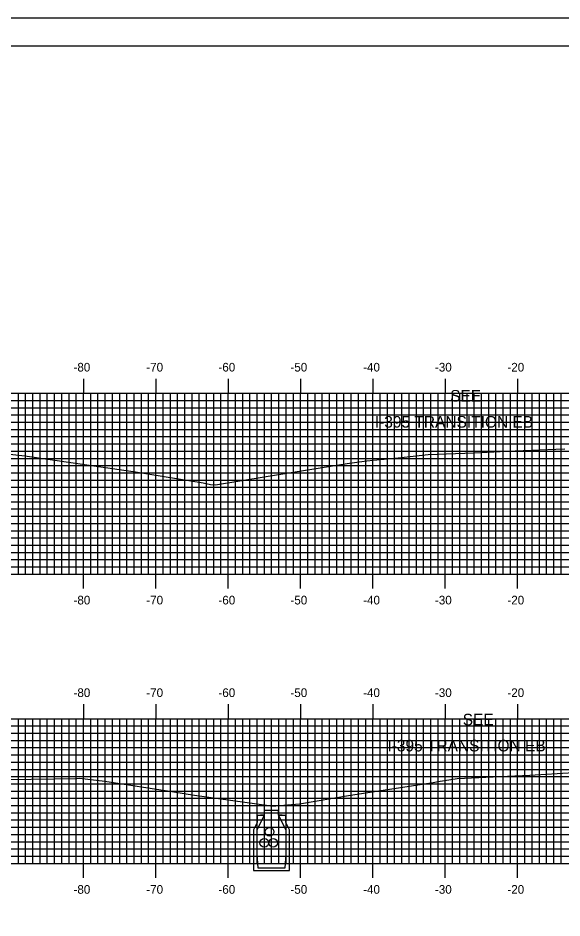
# Model space of a CAD drawing. Extents: x 842175 to 842518, y 363538 to 363758.
# Drawn here: x 842251.8 to 842327, y 363633.2 to 363757.6 of the extents above; entities that cross this region are included whole.
import ezdxf

# ---------------------------------------------------------------- set-up
doc = ezdxf.new("R2010")
doc.units = 0
for name, color, linetype in [('ANNOTATION', 7, 'Continuous'), ('BORDER', 7, 'Continuous'), ('H_V ANNOTATION', 7, 'Continuous'), ('MAJOR', 7, 'Continuous'), ('MINOR', 7, 'Continuous'), ('PLOT BOUNDARY', 7, 'Continuous'), ('S_Drainage_CB', 7, 'Continuous'), ('S_Drainage_Invert', 7, 'Continuous'), ('S_Roadway_Centerline', 7, 'Continuous')]:
    doc.layers.add(name, color=color, linetype=linetype)

msp = doc.modelspace()

# ---------------------------------------------------------------- linework, layer by layer
at = {"layer": 'BORDER'}
msp.add_lwpolyline([(842191.29, 363543.72), (842511.29, 363543.72), (842511.29, 363753.72), (842191.29, 363753.72)], close=True, dxfattribs=at)
at = {"layer": 'MAJOR'}
for p, q in [((842260.89, 363707.73), (842260.89, 363705.72)), ((842270.89, 363707.73), (842270.89, 363705.72)), ((842280.89, 363707.73), (842280.89, 363705.72)), ((842290.89, 363707.73), (842290.89, 363705.72)), ((842300.89, 363707.73), (842300.89, 363705.72)), ((842310.89, 363707.73), (842310.89, 363705.72)), ((842320.89, 363707.73), (842320.89, 363705.72)), ((842200.89, 363705.72), (842480.89, 363705.72)), ((842200.89, 363705.72), (842480.89, 363705.72)), ((842260.89, 363680.72), (842260.89, 363705.72)), ((842270.89, 363680.72), (842270.89, 363705.72)), ((842280.89, 363680.72), (842280.89, 363705.72)), ((842290.89, 363680.72), (842290.89, 363705.72)), ((842300.89, 363680.72), (842300.89, 363705.72)), ((842310.89, 363680.72), (842310.89, 363705.72)), ((842320.89, 363680.72), (842320.89, 363705.72)), ((842200.89, 363700.72), (842480.89, 363700.72)), ((842200.89, 363695.72), (842480.89, 363695.72)), ((842200.89, 363690.72), (842480.89, 363690.72)), ((842200.89, 363685.72), (842480.89, 363685.72)), ((842200.89, 363680.72), (842480.89, 363680.72)), ((842200.89, 363680.72), (842480.89, 363680.72)), ((842260.89, 363678.72), (842260.89, 363680.72)), ((842270.89, 363678.72), (842270.89, 363680.72)), ((842280.89, 363678.72), (842280.89, 363680.72)), ((842290.89, 363678.72), (842290.89, 363680.72)), ((842300.89, 363678.72), (842300.89, 363680.72)), ((842310.89, 363678.72), (842310.89, 363680.72)), ((842320.89, 363678.72), (842320.89, 363680.72)), ((842260.89, 363662.73), (842260.89, 363660.72)), ((842270.89, 363662.73), (842270.89, 363660.72)), ((842280.89, 363662.73), (842280.89, 363660.72)), ((842290.89, 363662.73), (842290.89, 363660.72)), ((842300.89, 363662.73), (842300.89, 363660.72)), ((842310.89, 363662.73), (842310.89, 363660.72)), ((842320.89, 363662.73), (842320.89, 363660.72)), ((842200.89, 363660.72), (842480.89, 363660.72)), ((842200.89, 363660.72), (842480.89, 363660.72)), ((842260.89, 363640.72), (842260.89, 363660.72)), ((842270.89, 363640.72), (842270.89, 363660.72)), ((842280.89, 363640.72), (842280.89, 363660.72)), ((842290.89, 363640.72), (842290.89, 363660.72)), ((842300.89, 363640.72), (842300.89, 363660.72)), ((842310.89, 363640.72), (842310.89, 363660.72)), ((842320.89, 363640.72), (842320.89, 363660.72)), ((842200.89, 363655.72), (842480.89, 363655.72)), ((842200.89, 363650.72), (842480.89, 363650.72)), ((842200.89, 363645.72), (842480.89, 363645.72)), ((842200.89, 363640.72), (842480.89, 363640.72)), ((842200.89, 363640.72), (842480.89, 363640.72)), ((842260.89, 363638.72), (842260.89, 363640.72)), ((842270.89, 363638.72), (842270.89, 363640.72)), ((842280.89, 363638.72), (842280.89, 363640.72)), ((842290.89, 363638.72), (842290.89, 363640.72)), ((842300.89, 363638.72), (842300.89, 363640.72)), ((842310.89, 363638.72), (842310.89, 363640.72)), ((842320.89, 363638.72), (842320.89, 363640.72))]:
    msp.add_line(p, q, dxfattribs=at)
at = {"layer": 'MINOR'}
for p, q in [((842251.89, 363680.72), (842251.89, 363705.72)), ((842252.89, 363680.72), (842252.89, 363705.72)), ((842253.89, 363680.72), (842253.89, 363705.72)), ((842254.89, 363680.72), (842254.89, 363705.72)), ((842255.89, 363680.72), (842255.89, 363705.72)), ((842256.89, 363680.72), (842256.89, 363705.72)), ((842257.89, 363680.72), (842257.89, 363705.72)), ((842258.89, 363680.72), (842258.89, 363705.72)), ((842259.89, 363680.72), (842259.89, 363705.72)), ((842261.89, 363680.72), (842261.89, 363705.72)), ((842262.89, 363680.72), (842262.89, 363705.72)), ((842263.89, 363680.72), (842263.89, 363705.72)), ((842264.89, 363680.72), (842264.89, 363705.72)), ((842265.89, 363680.72), (842265.89, 363705.72)), ((842266.89, 363680.72), (842266.89, 363705.72)), ((842267.89, 363680.72), (842267.89, 363705.72)), ((842268.89, 363680.72), (842268.89, 363705.72)), ((842269.89, 363680.72), (842269.89, 363705.72)), ((842271.89, 363680.72), (842271.89, 363705.72)), ((842272.89, 363680.72), (842272.89, 363705.72)), ((842273.89, 363680.72), (842273.89, 363705.72)), ((842274.89, 363680.72), (842274.89, 363705.72)), ((842275.89, 363680.72), (842275.89, 363705.72)), ((842276.89, 363680.72), (842276.89, 363705.72)), ((842277.89, 363680.72), (842277.89, 363705.72)), ((842278.89, 363680.72), (842278.89, 363705.72)), ((842279.89, 363680.72), (842279.89, 363705.72)), ((842281.89, 363680.72), (842281.89, 363705.72)), ((842282.89, 363680.72), (842282.89, 363705.72)), ((842283.89, 363680.72), (842283.89, 363705.72)), ((842284.89, 363680.72), (842284.89, 363705.72)), ((842285.89, 363680.72), (842285.89, 363705.72)), ((842286.89, 363680.72), (842286.89, 363705.72)), ((842287.89, 363680.72), (842287.89, 363705.72)), ((842288.89, 363680.72), (842288.89, 363705.72)), ((842289.89, 363680.72), (842289.89, 363705.72)), ((842291.89, 363680.72), (842291.89, 363705.72)), ((842292.89, 363680.72), (842292.89, 363705.72)), ((842293.89, 363680.72), (842293.89, 363705.72)), ((842294.89, 363680.72), (842294.89, 363705.72)), ((842295.89, 363680.72), (842295.89, 363705.72)), ((842296.89, 363680.72), (842296.89, 363705.72)), ((842297.89, 363680.72), (842297.89, 363705.72)), ((842298.89, 363680.72), (842298.89, 363705.72)), ((842299.89, 363680.72), (842299.89, 363705.72)), ((842301.89, 363680.72), (842301.89, 363705.72)), ((842302.89, 363680.72), (842302.89, 363705.72)), ((842303.89, 363680.72), (842303.89, 363705.72)), ((842304.89, 363680.72), (842304.89, 363705.72)), ((842305.89, 363680.72), (842305.89, 363705.72)), ((842306.89, 363680.72), (842306.89, 363705.72)), ((842307.89, 363680.72), (842307.89, 363705.72)), ((842308.89, 363680.72), (842308.89, 363705.72)), ((842309.89, 363680.72), (842309.89, 363705.72)), ((842311.89, 363680.72), (842311.89, 363705.72)), ((842312.89, 363680.72), (842312.89, 363705.72)), ((842313.89, 363680.72), (842313.89, 363705.72)), ((842314.89, 363680.72), (842314.89, 363705.72)), ((842315.89, 363680.72), (842315.89, 363705.72)), ((842316.89, 363680.72), (842316.89, 363705.72)), ((842317.89, 363680.72), (842317.89, 363705.72)), ((842318.89, 363680.72), (842318.89, 363705.72)), ((842319.89, 363680.72), (842319.89, 363705.72)), ((842321.89, 363680.72), (842321.89, 363705.72)), ((842322.89, 363680.72), (842322.89, 363705.72)), ((842323.89, 363680.72), (842323.89, 363705.72)), ((842324.89, 363680.72), (842324.89, 363705.72)), ((842325.89, 363680.72), (842325.89, 363705.72)), ((842326.89, 363680.72), (842326.89, 363705.72)), ((842200.89, 363704.72), (842480.89, 363704.72)), ((842200.89, 363703.72), (842480.89, 363703.72)), ((842200.89, 363702.72), (842480.89, 363702.72)), ((842200.89, 363701.72), (842480.89, 363701.72)), ((842200.89, 363699.72), (842480.89, 363699.72)), ((842200.89, 363698.72), (842480.89, 363698.72)), ((842200.89, 363697.72), (842480.89, 363697.72)), ((842200.89, 363696.72), (842480.89, 363696.72)), ((842200.89, 363694.72), (842480.89, 363694.72)), ((842200.89, 363693.72), (842480.89, 363693.72)), ((842200.89, 363692.72), (842480.89, 363692.72)), ((842200.89, 363691.72), (842480.89, 363691.72)), ((842200.89, 363689.72), (842480.89, 363689.72)), ((842200.89, 363688.72), (842480.89, 363688.72)), ((842200.89, 363687.72), (842480.89, 363687.72)), ((842200.89, 363686.72), (842480.89, 363686.72)), ((842200.89, 363684.72), (842480.89, 363684.72)), ((842200.89, 363683.72), (842480.89, 363683.72)), ((842200.89, 363682.72), (842480.89, 363682.72)), ((842200.89, 363681.72), (842480.89, 363681.72)), ((842251.89, 363640.72), (842251.89, 363660.72)), ((842252.89, 363640.72), (842252.89, 363660.72)), ((842253.89, 363640.72), (842253.89, 363660.72)), ((842254.89, 363640.72), (842254.89, 363660.72)), ((842255.89, 363640.72), (842255.89, 363660.72)), ((842256.89, 363640.72), (842256.89, 363660.72)), ((842257.89, 363640.72), (842257.89, 363660.72)), ((842258.89, 363640.72), (842258.89, 363660.72)), ((842259.89, 363640.72), (842259.89, 363660.72)), ((842261.89, 363640.72), (842261.89, 363660.72)), ((842262.89, 363640.72), (842262.89, 363660.72)), ((842263.89, 363640.72), (842263.89, 363660.72)), ((842264.89, 363640.72), (842264.89, 363660.72)), ((842265.89, 363640.72), (842265.89, 363660.72)), ((842266.89, 363640.72), (842266.89, 363660.72)), ((842267.89, 363640.72), (842267.89, 363660.72)), ((842268.89, 363640.72), (842268.89, 363660.72)), ((842269.89, 363640.72), (842269.89, 363660.72)), ((842271.89, 363640.72), (842271.89, 363660.72)), ((842272.89, 363640.72), (842272.89, 363660.72)), ((842273.89, 363640.72), (842273.89, 363660.72)), ((842274.89, 363640.72), (842274.89, 363660.72)), ((842275.89, 363640.72), (842275.89, 363660.72)), ((842276.89, 363640.72), (842276.89, 363660.72)), ((842277.89, 363640.72), (842277.89, 363660.72)), ((842278.89, 363640.72), (842278.89, 363660.72)), ((842279.89, 363640.72), (842279.89, 363660.72)), ((842281.89, 363640.72), (842281.89, 363660.72)), ((842282.89, 363640.72), (842282.89, 363660.72)), ((842283.89, 363640.72), (842283.89, 363660.72)), ((842284.89, 363640.72), (842284.89, 363660.72)), ((842285.89, 363640.72), (842285.89, 363660.72)), ((842286.89, 363640.72), (842286.89, 363660.72)), ((842287.89, 363640.72), (842287.89, 363660.72)), ((842288.89, 363640.72), (842288.89, 363660.72)), ((842289.89, 363640.72), (842289.89, 363660.72)), ((842291.89, 363640.72), (842291.89, 363660.72)), ((842292.89, 363640.72), (842292.89, 363660.72)), ((842293.89, 363640.72), (842293.89, 363660.72)), ((842294.89, 363640.72), (842294.89, 363660.72)), ((842295.89, 363640.72), (842295.89, 363660.72)), ((842296.89, 363640.72), (842296.89, 363660.72)), ((842297.89, 363640.72), (842297.89, 363660.72)), ((842298.89, 363640.72), (842298.89, 363660.72)), ((842299.89, 363640.72), (842299.89, 363660.72)), ((842301.89, 363640.72), (842301.89, 363660.72)), ((842302.89, 363640.72), (842302.89, 363660.72)), ((842303.89, 363640.72), (842303.89, 363660.72)), ((842304.89, 363640.72), (842304.89, 363660.72)), ((842305.89, 363640.72), (842305.89, 363660.72)), ((842306.89, 363640.72), (842306.89, 363660.72)), ((842307.89, 363640.72), (842307.89, 363660.72)), ((842308.89, 363640.72), (842308.89, 363660.72)), ((842309.89, 363640.72), (842309.89, 363660.72)), ((842311.89, 363640.72), (842311.89, 363660.72)), ((842312.89, 363640.72), (842312.89, 363660.72)), ((842313.89, 363640.72), (842313.89, 363660.72)), ((842314.89, 363640.72), (842314.89, 363660.72)), ((842315.89, 363640.72), (842315.89, 363660.72)), ((842316.89, 363640.72), (842316.89, 363660.72)), ((842317.89, 363640.72), (842317.89, 363660.72)), ((842318.89, 363640.72), (842318.89, 363660.72)), ((842319.89, 363640.72), (842319.89, 363660.72)), ((842321.89, 363640.72), (842321.89, 363660.72)), ((842322.89, 363640.72), (842322.89, 363660.72)), ((842323.89, 363640.72), (842323.89, 363660.72)), ((842324.89, 363640.72), (842324.89, 363660.72)), ((842325.89, 363640.72), (842325.89, 363660.72)), ((842326.89, 363640.72), (842326.89, 363660.72)), ((842200.89, 363659.72), (842480.89, 363659.72)), ((842200.89, 363658.72), (842480.89, 363658.72)), ((842200.89, 363657.72), (842480.89, 363657.72)), ((842200.89, 363656.72), (842480.89, 363656.72)), ((842200.89, 363654.72), (842480.89, 363654.72)), ((842200.89, 363653.72), (842480.89, 363653.72)), ((842200.89, 363652.72), (842480.89, 363652.72)), ((842200.89, 363651.72), (842480.89, 363651.72)), ((842200.89, 363649.72), (842480.89, 363649.72)), ((842200.89, 363648.72), (842480.89, 363648.72)), ((842200.89, 363647.72), (842480.89, 363647.72)), ((842200.89, 363646.72), (842480.89, 363646.72)), ((842200.89, 363644.72), (842480.89, 363644.72)), ((842200.89, 363643.72), (842480.89, 363643.72)), ((842200.89, 363642.72), (842480.89, 363642.72)), ((842200.89, 363641.72), (842480.89, 363641.72))]:
    msp.add_line(p, q, dxfattribs=at)
at = {"layer": 'PLOT BOUNDARY'}
msp.add_lwpolyline([(842175.1, 363537.6), (842515.1, 363537.6), (842515.1, 363757.6), (842175.1, 363757.6)], close=True, dxfattribs=at)
at = {"layer": 'S_Drainage_CB'}
for p, q in [((842285.85, 363647.36), (842284.87, 363647.36)), ((842284.87, 363647.36), (842284.87, 363646.38)), ((842284.87, 363645.36), (842285.85, 363647.36)), ((842288.87, 363647.36), (842287.85, 363647.36)), ((842287.85, 363647.36), (842288.87, 363645.36)), ((842288.87, 363646.38), (842288.87, 363647.36)), ((842284.87, 363646.38), (842284.37, 363645.36)), ((842289.36, 363645.36), (842288.87, 363646.38)), ((842284.37, 363645.36), (842284.37, 363639.72)), ((842284.87, 363642.05), (842284.87, 363645.36)), ((842288.87, 363645.36), (842288.87, 363642.05)), ((842289.36, 363639.72), (842289.36, 363645.36)), ((842285.03, 363640.05), (842284.87, 363642.05)), ((842288.87, 363642.05), (842288.7, 363640.05)), ((842284.37, 363639.72), (842289.36, 363639.72)), ((842288.7, 363640.05), (842285.03, 363640.05))]:
    msp.add_line(p, q, dxfattribs=at)
msp.add_lwpolyline([(842288.34, 363647.4), (842287.85, 363647.4), (842287.85, 363648.03), (842285.85, 363648.03), (842285.85, 363647.4), (842285.36, 363647.4)], dxfattribs=at)
at = {"layer": 'S_Drainage_Invert'}
for centre in [(842286.61, 363645.08), (842285.88, 363643.57), (842287.1, 363643.55)]:
    msp.add_circle(centre, 0.6, dxfattribs=at)
at = {"layer": 'S_Roadway_Centerline'}
for points in [[(842248.59, 363697.51), (842252.77, 363697.07), (842262.62, 363695.66), (842268.07, 363694.87), (842277.44, 363693.34), (842278.45, 363693.12), (842279.13, 363693.07), (842286.14, 363694.19), (842297.35, 363695.99), (842299.7, 363696.33), (842300.06, 363696.36), (842300.9, 363696.45), (842303.94, 363696.76), (842308.5, 363697.23), (842310.99, 363697.33), (842314.9, 363697.48), (842319.39, 363697.71), (842326.18, 363698), (842327.4, 363698.05)], [(842250.74, 363652.32), (842253.68, 363652.38), (842259.99, 363652.44), (842260.36, 363652.49), (842263.85, 363652.09), (842273.36, 363650.61), (842276.25, 363650.17), (842286.51, 363648.73), (842286.92, 363648.62), (842290.72, 363648.95), (842297.78, 363650.14), (842309.23, 363651.92), (842309.91, 363652.02), (842312.53, 363652.47), (842320.49, 363652.83), (842322.55, 363652.91), (842328.59, 363653.3)]]:
    msp.add_lwpolyline(points, dxfattribs=at)

# ---------------------------------------------------------------- texts
at = {"layer": 'ANNOTATION'}
for s, p in [('SEE', (842311.56, 363704.57)), ('I-395 TRANSITION EB', (842301.15, 363700.97)), ('SEE', (842313.3, 363659.8)), ('I-395 TRANSITION EB', (842302.89, 363656.2))]:
    msp.add_text(s, height=1.6, dxfattribs=at).set_placement(p)
at = {"layer": 'H_V ANNOTATION'}
for s, p in [('-80', (842259.51, 363708.72)), ('-70', (842269.57, 363708.72)), ('-60', (842279.54, 363708.72)), ('-50', (842289.49, 363708.72)), ('-40', (842299.54, 363708.72)), ('-30', (842309.46, 363708.72)), ('-20', (842319.47, 363708.72)), ('-80', (842259.51, 363676.52)), ('-70', (842269.57, 363676.52)), ('-60', (842279.54, 363676.52)), ('-50', (842289.49, 363676.52)), ('-40', (842299.54, 363676.52)), ('-30', (842309.46, 363676.52)), ('-20', (842319.47, 363676.52)), ('-80', (842259.51, 363663.72)), ('-70', (842269.57, 363663.72)), ('-60', (842279.54, 363663.72)), ('-50', (842289.49, 363663.72)), ('-40', (842299.54, 363663.72)), ('-30', (842309.46, 363663.72)), ('-20', (842319.47, 363663.72)), ('-80', (842259.51, 363636.52)), ('-70', (842269.57, 363636.52)), ('-60', (842279.54, 363636.52)), ('-50', (842289.49, 363636.52)), ('-40', (842299.54, 363636.52)), ('-30', (842309.46, 363636.52)), ('-20', (842319.47, 363636.52))]:
    msp.add_text(s, height=1.2, dxfattribs=at).set_placement(p)

doc.saveas('drawing.dxf')
